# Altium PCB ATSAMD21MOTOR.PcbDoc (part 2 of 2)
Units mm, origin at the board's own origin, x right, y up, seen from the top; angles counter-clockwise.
Board outline 45.2 x 50.2 mm, 4 copper layers (Top Layer, GND, POWER, Bottom Layer), stack 0.8 mm thick; 92 components, 102 nets, 421 pads, 273 vias.
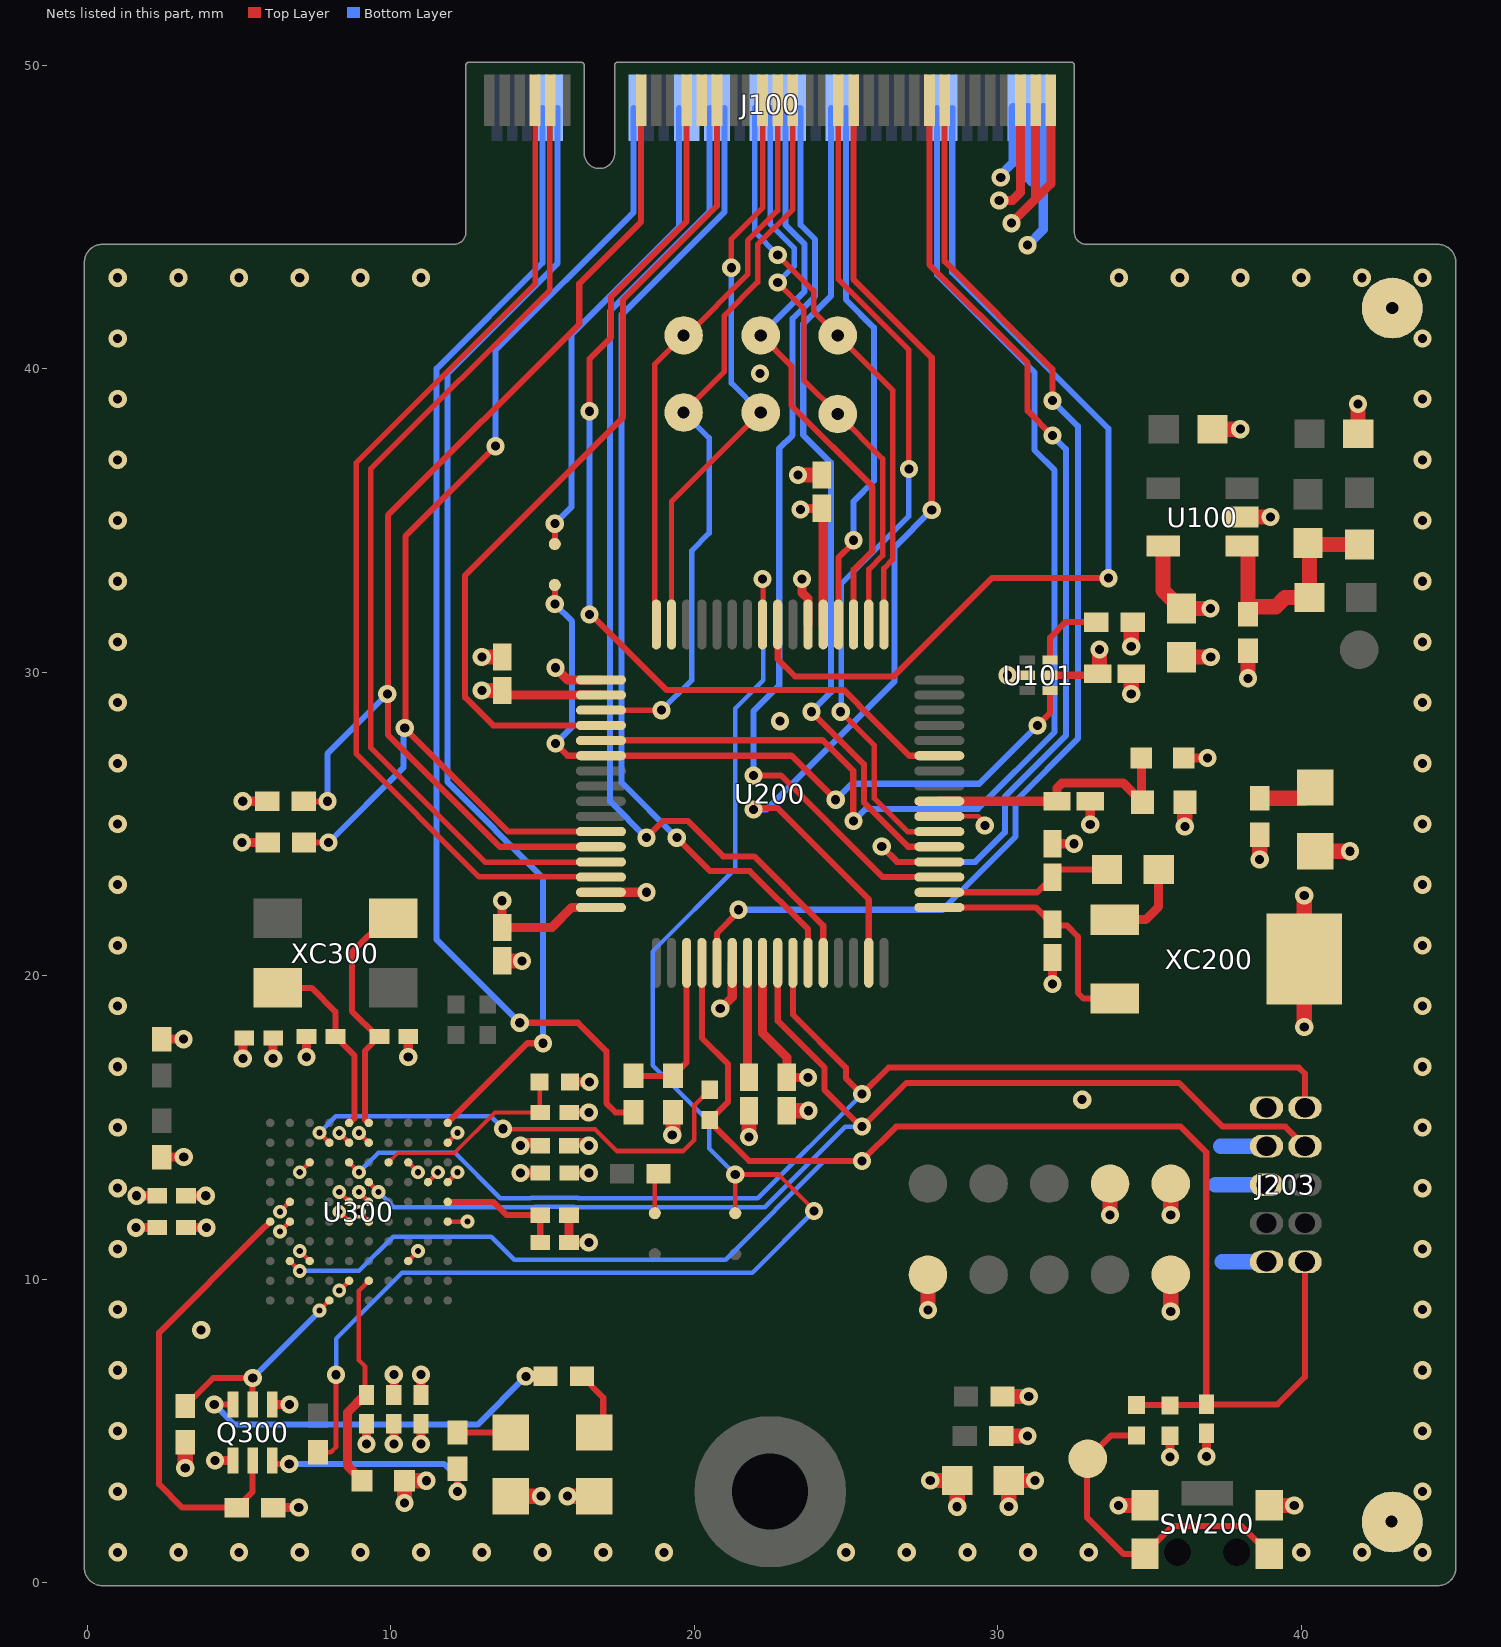
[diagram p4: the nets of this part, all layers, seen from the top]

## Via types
v1: diameter 0.6, hole 0.3, Top Layer to Bottom Layer, 234 vias
v2: diameter 0.457, hole 0.203, Top Layer to Bottom Layer, 30 vias
v3: diameter 0.8, hole 0.4, Top Layer to Bottom Layer, 8 vias
v4: diameter 0.457, hole 0.2, Top Layer to Bottom Layer, 1 vias

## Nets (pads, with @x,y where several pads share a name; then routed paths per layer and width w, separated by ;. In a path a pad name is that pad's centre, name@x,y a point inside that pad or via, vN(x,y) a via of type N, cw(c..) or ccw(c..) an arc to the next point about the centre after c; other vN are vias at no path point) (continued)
GND: C101.2 C102.1 C103.2 C104.2 C200.2 C201.2 C202.2 C203.2 C204.2 C205.2 C206.2 C207.2 C208.2 C209.2 C300.2 C301.2 C302.2 C303.2 C304.2 C305.2 C306.2 C307.2 C308.2 C309.2 C310.2 C311.2 C312.2 J100.64 J100.65 J100.66 J100.67 J203.3 J203.5 J203.9 pad.1 Q300.1 Q300.4 R103.1 R202.1 R204.1 R305.1 R310.1 SW200.2 SW200.4 TP107.1 TP300.1 U100.2 U101.2 U200.7 U200.22 U200.33 U200.47 U200.54 U300.B10 U300.C3 U300.C8 U300.E2 U300.E6 U300.F5 U300.F10 U300.H3 U300.H8 XC200.3 | length 67.9
  Top Layer w0.15: v2(6.351,12.224) U300.E2@6.676,12.549 ; v4(7.001,10.924) U300.H3@7.326,10.599 ; v2(7.001,13.524) U300.C3@7.326,13.849 ; v2(8.301,12.224) U300.F5@8.626,11.899 ; v2(8.951,12.874) U300.E6@9.276,12.549 ; U300.C8@10.576,13.849 v2(10.9,13.525) ; U300.H8@10.576,10.599 v2@10.902,10.925 ; U300.B10@11.876,14.499 v2(12.2,14.825) ; U300.F10@11.876,11.899 v2(12.525,11.899) ; U200.7@28.075,25.25 29.353,25.25 v1@29.653,24.95
  Top Layer w0.2: v1(30.32,29.9) U101.2@30.875,29.9
  Top Layer w0.3: v1@1.53,11.699 C309.2@2.251,11.699 ; v1@1.555,12.749 C311.2@2.276,12.749 ; v1(4.212,4.025) Q300.4@4.8,4.025 ; v1@5.125,17.204 C310.2@5.125,17.925 ; Q300.1@6.1,5.875 v1(6.661,5.875) ; R305.1@6.126,2.473 v1(6.968,2.473) ; v1@7.225,17.254 C300.2@7.225,17.975 ; v1(9.2,4.566) C303.2@9.2,5.235 ; v1(10.1,4.566) C308.2@10.1,5.235 ; v1@10.575,17.254 C301.2@10.575,17.975 ; v1(11,4.566) C312.2@11,5.235 ; v1(15.425,30.149) 15.824,29.75 U200.33@16.925,29.75 ; C305.2@15.876,12.11 C304.2@15.876,11.211 v1@16.597,11.211 ; C307.2@15.876,13.498 v1@16.597,13.498 ; C306.2@15.876,14.498 v1@16.597,14.498 ; C302.2@15.876,15.498 v1@16.597,15.498 ; R310.1@15.901,16.498 v1@16.622,16.498 ; U200.47@16.925,22.75 v1(18.425,22.75) ; v1@20.856,18.9 21.25,19.294 U200.54@21.25,20.425 ; v1(23.55,33.075) 23.55,32.625 23.75,32.425 U200.22@23.75,31.575 ; v1(30.45,44.798) 31.25,45.598 ; J100.65@31.25,48.85 31.25,45.598 ; J100.67@31.75,48.85 31.75,46.098 31.25,45.598 ; v1(31.8,19.723) C200.2@31.8,20.6 ; C201.2@31.8,24.35 v1(32.512,24.35) ; v1(33.05,24.982) C207.2@33.05,25.75 ; v1(36.881,4.157) C202.2@36.881,4.926
  Top Layer w0.5: v1(13,30.5) C204.2@13.676,30.5 ; C205.2@13.67,20.49 v1(14.32,20.49) ; v1(19.275,14.75) 19.3,14.775 R204.1@19.3,15.5 ; v1(21.8,14.682) C208.2@21.8,15.55 ; C206.2@23.05,15.55 v1(23.76,15.55) ; v1(23.418,36.5) C203.2@24.2,36.5 ; R202.1@30.154,6.136 v1(31.021,6.136) ; v1(33.7,12.119) TP300.1@33.7,13.15 ; v1(33.983,2.54) SW200.2@34.85,2.54 ; v1(34.4,29.287) C104.2@34.4,29.95 ; v1(35.7,12.119) TP107.1@35.7,13.15 ; C102.1@36.05,30.5 v1(37.019,30.5) ; v1(36.165,24.916) C209.2@36.165,25.718 ; C103.2@37.075,38.01 v1(37.993,38.01) ; U100.2@38.05,35.115 v1(38.988,35.115) ; v1(38.631,23.834) R103.1@38.631,24.65 ; SW200.4@38.95,2.54 v1(39.771,2.54) ; v1(40.1,18.314) XC200.3@40.1,20.55 v1(40.1,22.647) ; C101.2@41.875,37.86 v1(41.875,38.841)
  Bottom Layer w0.3: v1(30.984,44.074) 31.5,44.589 31.5,46.15 ; J100.64@31,48.6 31,46.279 31.129,46.15 31.5,46.15 ; J100.66@31.5,48.6 31.5,46.15
  Bottom Layer w0.5: 37.166,13.114 J203.5@38.856,13.114 ; 37.344,14.384 J203.3@38.856,14.384 ; 37.387,10.574 J203.9@38.856,10.574
  other v1: 1,1 3,1 5,1 7,1 9,1 11,1 13,1 15,1 17,1 19,1 25,1 27,1 29,1 31,1 33,1 40,1 42,1 44,1 1,3 44,3 1,5 44,5 1,7 44,7 3.751,8.326 1,9 44,9 1,11 44,11 16.526,11.211 1.601,11.699 1.626,12.749 1,13 44,13 16.526,13.498 16.525,14.4 1,15 44,15 16.526,15.498 32.782,15.916 16.551,16.498 1,17 44,17 5.125,17.275 7.225,17.325 10.575,17.325 20.856,18.925 1,19 44,19 1,21 44,21 1,23 44,23 29.575,24.95 1,25 44,25 1,27 44,27 22.825,28.389 1,29 44,29 1,31 44,31 1,33 44,33 1,35 44,35 1,37 44,37 1,39 44,39 22.168,39.841 1,41 44,41 1,43 3,43 5,43 7,43 9,43 11,43 34,43 36,43 38,43 40,43 42,43 44,43
  other v2: 10.901,10.927
  other v3: 42.974,2.014 43,42
GPIO1: J102.1 U101.4 U200.38 | length 24.7
  Top Layer w0.2: v1(15.406,32.245) J102.1@15.406,32.875 ; v1(15.425,27.65) 15.825,27.25 U200.38@16.925,27.25 23.208,27.25 v1(24.66,25.798) ; v1(31.315,28.25) 31.725,28.66 U101.4@31.725,29.4
  Bottom Layer w0.2: v1(15.406,32.245) 15.975,31.676 15.975,28.2 v1(15.425,27.65) ; v1(24.66,25.798) 25.188,26.326 29.391,26.326 v1(31.315,28.25)
GPIO2: J100.19 U200.11 | length 31.6
  Top Layer w0.2: v1(16.55,38.6) 16.55,40.329 17.259,41.038 17.259,42.371 19.75,44.862 J100.19@19.75,48.85 ; v1@16.6,31.9 19.088,29.412 24.941,29.412 25.425,28.928 25.425,28.916 27.091,27.25 U200.11@28.075,27.25
  Bottom Layer w0.2: v1@16.55,31.95 v1(16.55,38.6)
  other v1: 16.55,31.9
GPIO3: J100.20
GPIO4: J100.21
GPIO5: J100.22 U200.60 | length 34.6
  Top Layer w0.2: v1(18.425,24.55) 18.975,25.1 19.785,25.1 20.954,23.93 21.974,23.93 24.25,21.654 U200.60@24.25,20.425
  Bottom Layer w0.2: v1(18.425,24.55) 17.228,25.747 17.228,41.908 20.5,45.18 J100.22@20.5,48.6
GPIO6: J100.23 U200.36 | length 28
  Top Layer w0.2: U200.36@16.925,28.25 13.372,28.25 12.45,29.172 12.45,33.191 17.65,38.391 17.65,42.267 20.75,45.367 J100.23@20.75,48.85
GPIO7: J100.24 U200.59 | length 32.9
  Top Layer w0.2: v1(19.425,24.55) 20.528,23.447 21.828,23.447 23.75,21.526 U200.59@23.75,20.425
  Bottom Layer w0.2: v1(19.425,24.55) 17.607,26.368 17.607,41.782 21,45.175 J100.24@21,48.6
HALL1: J100.51 U200.4 | length 33.6
  Top Layer w0.2: v1(26.178,24.259) 26.687,23.75 U200.4@28.075,23.75 ; J100.51@27.75,48.85 27.75,43.432 30.986,40.195 30.986,38.614 v1(31.8,37.8)
  Bottom Layer w0.2: v1(26.178,24.259) 26.687,23.75 29.259,23.75 30.236,24.727 30.236,25.898 32.247,27.91 32.247,37.353 v1(31.8,37.8)
HALL2: J100.52 U200.37 | length 40.4
  Top Layer w0.2: U200.37@16.925,27.75 16.935,27.76 24.229,27.76 25.238,26.751 25.238,25.112 v1(25.25,25.1)
  Bottom Layer w0.2: v1(25.25,25.1) 25.65,25.5 29.343,25.5 31.875,28.032 31.875,36.653 31.211,37.317 31.211,39.882 28,43.093 J100.52@28,48.6
HALL3: J100.53 U200.53 | length 39.1
  Top Layer w0.2: U200.53@20.75,20.425 20.75,21.397 21.455,22.102 v1(21.455,22.175) ; J100.53@28.25,48.85 28.25,43.537 31.8,39.987 v1(31.8,38.95)
  Bottom Layer w0.2: v1(21.455,22.175) 28.179,22.175 30.586,24.582 30.586,25.753 32.643,27.811 32.643,38.107 v1(31.8,38.95)
HALL_TRX_OE: J100.54 U200.24 | length 31.3
  Top Layer w0.2: U200.24@22.8,31.625 U200.24@22.75,31.575 22.75,30.435 23.319,29.866 26.573,29.866 29.807,33.1 v1(33.65,33.1)
  Bottom Layer w0.2: J100.54@28.5,48.6 28.5,43.177 33.65,38.027 v1(33.65,33.1)
ISENSE_COMMON: J100.34 U200.3 | length 30.6
  Top Layer w0.2: v1(21.95,26.6) 22.857,26.6 26.207,23.25 U200.3@28.075,23.25
  Bottom Layer w0.2: v1(21.95,26.6) 21.95,28.719 22.8,29.569 22.8,37.375 23.242,37.817 23.242,41.657 23.98,42.395 23.98,44.259 23.5,44.739 J100.34@23.5,48.6
MCU_USB_N: J100.9 U200.45 | length 32.9
  Top Layer w0.18: J100.9@15.25,48.85 15.25,48.373 15.24,48.363 15.24,42.602 9.346,36.708 9.346,27.506 13.112,23.74 16.915,23.74 U200.45@16.925,23.75
MCU_USB_P: J100.7 U200.46 | length 33.7
  Top Layer w0.18: J100.7@14.75,48.85 14.75,48.421 14.76,48.411 14.76,42.801 8.866,36.907 8.866,27.307 12.913,23.26 16.915,23.26 U200.46@16.925,23.25
MOTOR_VDC: J100.41 U200.63 | length 34.3
  Top Layer w0.2: v1(21.95,25.475) 21.997,25.522 22.747,25.522 25.75,22.519 U200.63@25.75,20.425 ; J100.41@25.25,48.85 25.25,42.94 27.825,40.365 v1(27.825,35.35)
  Bottom Layer w0.2: v1(21.95,25.475) 22.378,25.475 26.601,29.698 26.601,34.126 v1(27.825,35.35)
NetC100_2: C100.2 R100.2 R101.1 R102.1 U100.1 | length 7.7
  Top Layer w0.5: U100.1@38.05,34.165 38.25,33.964 38.25,32.16 39.166,32.16 39.465,32.46 R102.1@40.275,32.46 C100.2@40.275,34.21 ; C100.2@40.225,34.26 C100.2@40.275,34.21 ; R100.2@41.925,34.21 C100.2@40.275,34.21
NetC302_1: C302.1 R310.2 U300.C7 | length 6.7
  Top Layer w0.125: U300.C7@9.926,13.849 10.229,14.152 12.086,14.152 13.433,15.498 C302.1@14.926,15.498
  Top Layer w0.15: C302.1@14.901,15.523 R310.2@14.901,16.498
NetC303_1: C303.1 L300.2 U300.J6 | length 7.2
  Top Layer w0.15: C303.1@9.151,6.185 9.151,7.128 8.951,7.327 8.951,9.624 U300.J6@9.276,9.949
  Top Layer w0.3: L300.2@9.058,3.373 8.57,3.861 8.57,5.605 C303.1@9.151,6.185
NetC304_1: C304.1 C305.1 U300.E10 | length 4.1
  Top Layer w0.2: U300.E10@11.876,12.549 13.376,12.549 13.815,12.11 C305.1@14.926,12.11 C304.1@14.926,11.211
NetD100_1: D100.1 R103.2 | length 2
  Top Layer w0.5: R103.2@38.631,25.85 40.113,25.85 D100.1@40.465,26.203
NetD300_1: D300.1 R303.2 | length 1.8
  Top Layer w0.2: R303.2@12.2,4.95 D300.1@13.95,4.95
NetD301_1: D301.1 R304.2 | length 2.4
  Top Layer w0.2: R304.2@16.15,6.65 R304.2@16.3,6.8 17,6.1 D301.1@17,4.95
NetJ100_18: J100.18 J102.2 | length 16.1
  Top Layer w0.2: J102.2@15.406,34.225 v1(15.406,34.896)
  Bottom Layer w0.2: v1(15.406,34.896) 15.95,35.44 15.95,41.125 19.5,44.675 J100.18@19.5,48.6
NetJ201_2: J201.2 R306.1 | length 1.3
  Top Layer w0.15: J201.2@18.7,12.175 18.7,13.355 R306.1@18.819,13.474
NetJ202_1: J202.1 XC200.1 | length 2.8
  Top Layer w0.3: XC200.1@33.85,21.85 34.872,21.85 35.3,22.278 J202.1@35.3,23.5
NetQ300_3: Q300.3 R304.1 | length 12.5
  Top Layer w0.2: v1(4.184,5.875) Q300.3@4.8,5.875 ; v1(14.45,6.8) R304.1@15.1,6.8
  Bottom Layer w0.2: v1(4.184,5.875) 4.849,5.21 12.86,5.21 v1(14.45,6.8)
NetQ300_6: Q300.6 R303.1 | length 7.5
  Top Layer w0.2: Q300.6@6.1,4.025 6.215,3.91 v1(6.654,3.91) ; v1(12.2,3.005) R303.1@12.2,3.75
  Bottom Layer w0.2: v1(6.654,3.91) 11.759,3.91 12.2,3.469 v1(12.2,3.005)
NetR104_1: R104.1 U101.6 | length 2.5
  Top Layer w0.2: U101.6@31.725,30.4 31.725,31.144 32.231,31.65 R104.1@33.25,31.65
NetR208_1: R208.1 SW200.1 SW200.5 TP200.1 | length 11.9
  Top Layer w0.2: TP200.1@33.187,4.085 33.078,4.194 TP200.1@32.97,4.303 ; R208.1@34.573,4.852 33.736,4.852 TP200.1@32.97,4.085 TP200.1@32.97,4.303 ; SW200.1@34.85,0.94 34.148,0.94 32.945,2.143 32.945,4.318 32.955,4.318 TP200.1@32.97,4.303 ; SW200.1@34.85,0.95 35.772,1.872 38.028,1.872 SW200.5@38.95,0.95
PA00_XIN32: C200.1 U200.1 XC200.2 | length 7.8
  Top Layer w0.2: U200.1@28.075,22.25 31.25,22.25 C200.1@31.8,21.7 ; 32.1,21.65 32.284,21.65 32.641,21.293 32.641,19.431 32.822,19.25 XC200.2@33.85,19.25
PA01_XOUT32: C201.1 J202.2 U200.2 | length 5.8
  Top Layer w0.2: U200.2@28.075,22.75 31.3,22.75 C201.1@31.8,23.25 32.05,23.5 J202.2@33.6,23.5
PA08_TCC0_WO0: J100.28 TP100.1 U200.17 | length 19
  Top Layer w0.18: v1(22.75,43.75) 23.935,42.565 23.935,41.895 v3(24.73,41.1) 26.535,39.295 26.535,33.708 26.25,33.423 U200.17@26.25,31.575
  Bottom Layer w0.18: J100.28@22,48.6 22,44.5 v1(22.75,43.75)
PA09_TCC0_WO1: J100.30 TP102.1 U200.18 | length 19.2
  Top Layer w0.18: v1(22.75,42.839) 23.605,41.985 23.605,39.635 v3(24.73,38.51) 26.205,37.035 26.205,33.845 25.75,33.39 U200.18@25.75,31.575
  Bottom Layer w0.18: J100.30@22.5,48.6 22.5,44.764 23.29,43.974 23.29,43.379 v1(22.75,42.839)
PA10_TCC0_WO2: J100.32 TP104.1 U200.19 | length 19.7
  Top Layer w0.2: v3(22.19,41.1) 23.198,40.092 23.198,38.79 25.865,36.123 25.865,33.996 25.25,33.381 U200.19@25.25,31.575
  Bottom Layer w0.2: v3(22.19,41.1) 23.63,42.54 23.63,44.115 23,44.745 J100.32@23,48.6
PA11_ADC_AIN19: J100.40 U200.20 | length 17.9
  Top Layer w0.2: U200.20@24.75,31.575 24.75,33.775 25.25,34.275 v1(25.25,34.35)
  Bottom Layer w0.2: J100.40@25,48.6 25,42.277 25.919,41.358 25.919,36.302 25.25,35.633 v1(25.25,34.35)
PA14_TCC0_WO4: J100.29 TP101.1 U200.31 | length 19.3
  Top Layer w0.18: U200.31@19.25,31.575 19.25,35.62 v3(22.19,38.56) ; v1(21.221,43.331) 21.221,44.275 22.25,45.304 J100.29@22.25,48.85
  Bottom Layer w0.18: v1(21.221,43.331) 21.221,39.529 v3(22.19,38.56)
PA15_TCC0_WO5: J100.31 TP103.1 U200.32 | length 19.3
  Top Layer w0.18: U200.32@18.75,31.575 18.697,31.628 18.697,40.148 v3(19.65,41.1) 19.754,41.1 21.761,43.107 21.761,44.225 22.75,45.214 J100.31@22.75,48.85 ; TP103.1@19.83,40.92 20,41.09 TP103.1@20,41.1
PA16_TCC0_WO6: J100.33 TP105.1 U200.35 | length 24.6
  Top Layer w0.18: U200.35@16.925,28.75 v1(18.925,28.75) ; v3(19.65,38.56) 20.985,39.895 20.985,41.746 22.091,42.852 22.091,44.088 23.25,45.247 J100.33@23.25,48.85
  Bottom Layer w0.18: v1(18.925,28.75) 19.91,29.735 19.91,34.001 20.49,34.581 20.49,37.72 v3(19.65,38.56)
PA22_S3_PAD0: J100.12 R206.1 U200.43 | length 37.1
  Top Layer w0.2: R206.1@7.143,24.391 v1(7.949,24.391) ; v1(13.45,37.45) 10.48,34.48 10.48,28.181 v1(10.46,28.161) 13.871,24.75 U200.43@16.925,24.75
  Bottom Layer w0.2: v1(7.949,24.391) 10.414,26.856 10.414,28.115 v1(10.46,28.161) ; v1(13.45,37.45) 13.45,40.605 18,45.155 J100.12@18,48.6
PA23_S3_PAD1: J100.13 R205.1 U200.44 | length 38.1
  Top Layer w0.2: R205.1@7.129,25.748 v1(7.911,25.748) ; U200.44@16.925,24.25 13.593,24.25 9.904,27.939 9.904,35.168 16.209,41.473 16.209,42.806 18.25,44.847 J100.13@18.25,48.85
  Bottom Layer w0.2: v1(7.911,25.748) 7.911,27.309 v1(9.886,29.284)
PA27_USB_VBUS: R203.1 R204.2 U200.51 | length 5.2
  Top Layer w0.2: R203.1@18,16.7 R204.2@19.3,16.7 19.75,17.15 U200.51@19.75,20.425
PA30_SWDCLK: J203.4 U200.57 U300.D6 | length 40.3
  Top Layer w0.15: U300.D6@9.276,13.199 v2(9.6,12.875)
  Top Layer w0.2: U200.57@22.75,20.425 22.75,18.514 24.293,16.97 24.293,16.232 25.525,15 26.991,16.466 35.975,16.466 37.412,15.029 39.481,15.029 J203.4@40.126,14.384
  Bottom Layer w0.15: v2(9.6,12.875) 10.102,12.373 14.742,12.373 14.751,12.382 16.051,12.382 16.06,12.373 22.319,12.373 24.975,15.029 v1(25.525,15.029)
PA31_SWDIO: J203.2 U200.58 U300.C5 | length 40.8
  Top Layer w0.15: U300.C5@8.626,13.849 v2(8.95,13.525)
  Top Layer w0.2: U200.58@23.25,20.425 23.25,18.723 24.998,16.975 24.998,16.627 v1(25.525,16.1) 26.4,16.975 39.922,16.975 40.126,16.771 J203.2@40.126,15.654
  Bottom Layer w0.15: v2(8.95,13.525) 9.586,14.161 12.119,14.161 13.607,12.673 14.618,12.673 14.627,12.682 16.175,12.682 16.184,12.673 22.098,12.673 v1(25.525,16.1)
PB04_ADC_AIN12: J100.38 U200.5 | length 27.7
  Top Layer w0.2: v1@23.858,28.723 v1(23.858,28.7) 25.588,26.97 25.588,25.712 27.05,24.25 U200.5@28.075,24.25
  Bottom Layer w0.2: v1(23.858,28.7) 24.5,29.342 24.5,36.904 23.592,37.812 23.592,41.484 24.5,42.392 J100.38@24.5,48.6
PB05_ADC_AIN13: J100.39 U200.6 | length 28
  Top Layer w0.18: J100.39@24.75,48.85 24.75,42.948 27.075,40.623 v1(27.075,36.7) ; v1(24.825,28.7) 25.928,27.597 25.928,25.853 27.031,24.75 U200.6@28.075,24.75
  Bottom Layer w0.18: v1(24.825,28.7) 24.84,28.715 24.84,32.909 27.075,35.144 v1(27.075,36.7)
PB12_S4_PAD0: J200.1 R307.2 U200.25 | length 49.9
  Top Layer w0.15: R307.2@7.6,4.3 8.025,4.3 8.195,4.47 8.195,6.849 v1(8.196,6.85) ; J200.1@21.35,12.175 v1(21.35,13.45) 22.775,13.45 v1@23.962,12.263 ; U200.25@22.25,31.575 v1@22.25,33
  Bottom Layer w0.15: v1(8.196,6.85) 8.196,8.044 10.37,10.217 21.917,10.217 v1(23.95,12.25) 23.95,12.291 23.958,12.298 v1@23.978,12.278 ; v1(21.35,13.45) 20.493,14.307 20.493,15.182 18.625,17.05 18.625,20.798 21.35,23.523 21.35,28.808 22.275,29.733 22.275,33.05 v1(22.25,33.075)
POWER_LED_CTRL: Q300.2 R302.1 U300.K4 | length 7.1
  Top Layer w0.15: v2(7.651,8.974) U300.K4@7.976,9.299
  Top Layer w0.2: R302.1@3.226,5.823 4.147,6.744 v1(5.45,6.744) Q300.2@5.45,5.875
  Bottom Layer w0.2: v1(5.45,6.744) 7.651,8.945 v2(7.651,8.974)
STATUS_LED_CTRL: Q300.5 R305.2 U300.F1 | length 14.8
  Top Layer w0.2: Q300.5@5.45,4.025 5.45,2.997 R305.2@4.926,2.473 3.134,2.473 2.363,3.244 2.363,8.236 5.701,11.574 U300.F1@6.026,11.899
TARGET_RESET: R200.1 U300.B4 | length 15.2
  Top Layer w0.15: v2(7.65,14.825) U300.B4@7.975,14.5 ; v1@13.974,14.937 16.731,14.937 17.442,14.225 19.633,14.225 19.996,14.588 19.996,15.725 R200.1@20.514,16.243
  Bottom Layer w0.15: v2(7.65,14.825) 8.19,15.365 13.294,15.365 v1(13.701,14.958)
TARGET_RESET_SENSE: C202.1 J203.10 R200.2 R207.1 R208.2 U200.52 U300.H2 | length 62.7
  Top Layer w0.15: U300.H2@6.675,10.6 v2(7,10.275)
  Top Layer w0.2: U200.52@20.25,20.425 20.25,17.949 21.116,17.083 21.116,15.845 R200.2@20.514,15.243 20.514,15.189 21.804,13.9 v1(25.525,13.9) 26.654,15.029 36.025,15.029 36.87,14.184 36.87,5.887 C202.1@36.881,5.876 ; R208.2@34.573,5.852 36.857,5.852 C202.1@36.881,5.876 ; J203.10@40.126,10.574 40.126,6.783 39.218,5.876 C202.1@36.881,5.876
  Bottom Layer w0.15: v2(7,10.275) 8.952,10.275 10.081,11.404 13.308,11.404 14.067,10.646 21.033,10.646 24.287,13.9 v1(25.525,13.9)
VCC_EDBG_P3V3: C306.1 C307.1 C308.1 C309.1 C310.1 C311.1 C312.1 D300.2 D301.2 L300.1 R300.2 R301.2 R302.2 R311.1 TP307.1 U300.B5 U300.B6 U300.D9 U300.D10 U300.E5 U300.F2 U300.F6 U300.J5 | length 17.4
  Top Layer w0.15: v2(6.351,11.574) U300.F2@6.676,11.899 ; v2(8.301,9.624) U300.J5@8.626,9.949 ; v2(8.301,12.874) U300.E5@8.626,12.549 ; v2(8.301,14.824) U300.B5@8.626,14.499 ; v2(8.951,12.224) U300.F6@9.276,11.899 ; v2(8.951,14.824) U300.B6@9.276,14.499 ; U300.D9@11.226,13.199 v2(11.55,13.525) ; U300.D10@11.876,13.199 v2(12.2,13.525)
  Top Layer w0.3: R300.2@2.45,17.91 v1(3.17,17.91) ; R301.2@2.452,14.022 v1(3.178,14.022) ; C311.1@3.251,12.749 v1@3.972,12.749 ; C309.1@3.276,11.699 v1@3.997,11.699 ; v1@6.125,17.204 C310.1@6.125,17.925 ; C308.1@10.1,6.185 v1(10.1,6.854) ; C312.1@11,6.185 v1(11,6.854) ; v1@14.205,13.498 C307.1@14.926,13.498 ; v1@14.276,14.498 C306.1@14.926,14.498
  Top Layer w0.5: v1(3.226,3.783) R302.2@3.226,4.623 ; v1(10.45,2.627) L300.1@10.45,3.36 v1(11.171,3.36) ; D300.2@13.95,2.85 v1(14.956,2.85) ; v1(15.827,2.85) D301.2@17,2.85 ; v1(27.7,8.988) TP307.1@27.7,10.15 ; v1(27.776,3.368) R311.1@28.663,3.368 v1(28.663,2.501)
  other v1: 3.926,11.699 3.901,12.749 14.276,13.498 14.275,14.4 6.125,17.275
VCC_EDBG_USB_P5V0: J100.10 U300.A10 | length 37.9
  Top Layer w0.2: U300.A10@11.876,15.149 14.501,17.774 v1(15.012,17.774)
  Bottom Layer w0.2: v1(15.012,17.774) 15.012,23.236 11.862,26.385 11.862,39.839 15.5,43.476 J100.10@15.5,48.6
VCC_MCU_CORE: C208.1 U200.55 | length 3.8
  Top Layer w0.3: U200.55@21.75,20.425 21.75,16.7 C208.1@21.8,16.65
VCC_MCU_VDDANA: C207.1 C209.1 L200.2 U200.8 | length 8.9
  Top Layer w0.3: U200.8@28.075,25.75 C207.1@31.95,25.75 31.95,26.18 32.12,26.35 34.136,26.35 C209.1@34.732,25.754 ; L200.2@34.732,27.171 C209.1@34.732,25.754 ; C209.1@34.768,25.718 C209.1@34.732,25.754
VCC_TARGET_P3V3: C102.2 C104.1 C203.1 C204.1 C205.1 C206.1 D100.2 J100.62 J100.63 J203.1 L200.1 R101.2 R104.2 R201.2 R205.2 R206.2 R207.2 R311.2 TP108.1 U100.5 U101.5 U200.21 U200.34 U200.48 U200.56 | length 39.7
  Top Layer w0.25: U101.5@31.725,29.9 33.25,29.9 C104.1@33.3,29.95
  Top Layer w0.3: v1(5.096,24.391) R206.2@5.943,24.391 ; v1(5.122,25.748) R205.2@5.929,25.748 ; v1(13.67,22.472) C205.1@13.67,21.59 15.306,21.59 15.966,22.25 U200.48@16.925,22.25 ; C204.1@13.676,29.4 13.826,29.25 U200.34@16.925,29.25 ; U200.56@22.25,20.425 22.25,18.108 23.05,17.308 C206.1@23.05,16.65 v1(23.743,16.65) ; v1@23.437,35.4 C203.1@24.2,35.4 24.25,35.35 U200.21@24.25,31.575 ; v1(30.05,45.55) 30.487,45.55 30.75,45.813 J100.63@30.75,48.85 ; v1(35.675,4.146) R207.2@35.675,4.839 ; L200.1@36.132,27.171 v1(36.908,27.171)
  Top Layer w0.5: v1(13,29.4) C204.1@13.676,29.4 ; R201.2@30.113,4.835 v1(30.98,4.835) ; v1(30.363,2.504) R311.2@30.363,3.368 v1(31.228,3.368) ; C104.1@33.35,30 v1(33.35,30.75) ; v1(34.4,30.85) 34.4,31.6 R104.2@34.45,31.65 ; U100.5@35.45,34.165 35.45,32.7 C102.2@36.05,32.1 v1(37.011,32.1) ; v1(35.7,8.939) TP108.1@35.7,10.15 ; v1(38.25,29.8) R101.2@38.25,30.71 ; D100.2@40.465,24.103 v1(41.605,24.103)
  Bottom Layer w0.3: v1(30.1,46.3) 30.013,46.3 30.5,46.787 J100.62@30.5,48.6
  other v1: 23.5,35.36
VCC_TARGET_USB_P5V0: J100.8 R203.2 | length 38.9
  Top Layer w0.2: v1(14.25,18.45) 16.166,18.45 17.101,17.515 17.101,15.803 17.404,15.5 R203.2@18,15.5 R203.2@18,15.692
  Bottom Layer w0.2: v1(14.25,18.45) 11.512,21.188 11.512,40.005 15,43.492 J100.8@15,48.6
XIN0: C300.1 U300.A5 XC300.1 | length 6.2
  Top Layer w0.2: XC300.1@6.276,19.599 7.39,19.599 8.175,18.814 C300.1@8.175,18 8.8,17.375 8.8,15.298 U300.A5@8.626,15.124
XOUT0: C301.1 U300.A6 XC300.3 | length 8.1
  Top Layer w0.2: U300.A6@9.276,15.123 9.15,15.249 9.15,17.525 C301.1@9.625,18 9.552,18 8.719,18.833 8.719,20.772 9.846,21.899 XC300.3@10.076,21.899
pads on no net: J100.2 J100.5 J100.11 J100.59 J100.60 J100.61 J203.6 J203.7 J203.8 SW200.3 SW200.6 SW200.7 U300.A2 U300.A3 U300.A4 U300.A7 U300.B1 U300.B3 U300.B7 U300.C1 U300.C2 U300.C4 U300.C6 U300.C9 U300.C10 U300.D1 U300.D2 U300.D3 U300.D4 U300.D5 U300.D7 U300.D8 U300.E1 U300.E3 U300.E4 U300.E7 U300.E8 U300.F3 U300.F4 U300.F7 U300.F8 U300.G1 U300.G2 U300.G3 U300.G4 U300.G6 U300.G7 U300.G8 U300.G9 U300.G10 U300.H1 U300.H4 U300.H5 U300.H6 U300.H10 U300.J1 U300.J2 U300.J3 U300.J7 U300.J10 U300.K1 U300.K5 U300.K6 U300.K7 XC300.2 XC300.4

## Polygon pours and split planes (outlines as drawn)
GND on Top Layer "Mechanical 1-No Net" (solid, remove dead copper, pour order 4): -0.4,-1.776 -0.4,50.32 43.687,50.32 45.153,50.32 45.153,-1.762
GND on Bottom Layer "Mechanical 1-No Net" (solid, remove dead copper, pour order 3): -0.4,-1.776 -0.4,50.32 43.687,50.32 45.153,50.32 45.153,-1.762
GND on GND (split plane): 32.224,44.5 32.223,44.5 32.232,44.39 32.258,44.283 32.3,44.181 32.357,44.088 32.429,44.004 32.512,43.932 32.606,43.875 32.708,43.833 32.815,43.807 32.925,43.798 32.925,43.799 44.5,43.799 44.502,43.799 44.558,43.794 44.615,43.776 44.666,43.749 44.712,43.712 44.749,43.666 44.776,43.615 44.794,43.558 44.799,43.502 44.799,43.5 44.799,0.5 44.799,0.498 44.794,0.442 44.776,0.385 44.749,0.334 44.712,0.288 44.666,0.251 44.615,0.223 44.558,0.206 44.502,0.201 44.5,0.201 0.5,0.201 0.499,0.201 0.497,0.201 0.442,0.206 0.385,0.223 0.334,0.251 0.288,0.288 0.251,0.334 0.223,0.385 0.206,0.442 0.201,0.498 0.201,0.5 0.201,43.5 0.201,43.502 0.206,43.558 0.223,43.615 0.251,43.666 0.288,43.712 0.334,43.749 0.385,43.776 0.442,43.794 0.498,43.799 0.5,43.799 12.075,43.799 12.075,43.798 12.185,43.807 12.292,43.833 12.394,43.875 12.487,43.932 12.571,44.004 12.643,44.088 12.7,44.181 12.742,44.283 12.768,44.39 12.777,44.5 12.776,44.5 12.776,49.799 16.074,49.799 16.074,47.1 16.073,47.1 16.083,46.975 16.112,46.852 16.16,46.736 16.226,46.629 16.308,46.533 16.404,46.451 16.511,46.385 16.627,46.337 16.75,46.308 16.875,46.298 17,46.308 17.123,46.337 17.239,46.385 17.346,46.451 17.442,46.533 17.524,46.629 17.59,46.736 17.638,46.852 17.667,46.975 17.677,47.1 17.676,47.1 17.676,49.799 32.224,49.799
VCC_EDBG_P3V3 on POWER (split plane): 22.942,11.197 22.994,11.157 23.055,11.132 23.12,11.123 29.27,11.123 29.27,0.201 0.5,0.201 0.499,0.201 0.497,0.201 0.442,0.206 0.385,0.223 0.334,0.251 0.288,0.288 0.251,0.334 0.223,0.385 0.206,0.442 0.201,0.498 0.201,0.5 0.201,22.903 11.235,22.903
VCC_TARGET_P3V3 on POWER (split plane): 32.224,44.5 32.223,44.5 32.232,44.39 32.258,44.283 32.3,44.181 32.357,44.088 32.429,44.004 32.512,43.932 32.606,43.875 32.708,43.833 32.815,43.807 32.925,43.798 32.925,43.799 44.5,43.799 44.502,43.799 44.558,43.794 44.615,43.776 44.666,43.749 44.712,43.712 44.749,43.666 44.776,43.615 44.794,43.558 44.799,43.502 44.799,43.5 44.799,0.5 44.799,0.498 44.794,0.442 44.776,0.385 44.749,0.334 44.712,0.288 44.666,0.251 44.615,0.223 44.558,0.206 44.502,0.201 44.5,0.201 29.775,0.201 29.775,11.375 29.766,11.44 29.741,11.501 29.701,11.553 29.649,11.594 29.588,11.619 29.523,11.627 23.224,11.627 11.518,23.334 11.466,23.374 11.405,23.399 11.34,23.407 0.201,23.407 0.201,43.5 0.201,43.502 0.206,43.558 0.223,43.615 0.251,43.666 0.288,43.712 0.334,43.749 0.385,43.776 0.442,43.794 0.498,43.799 0.5,43.799 12.075,43.799 12.075,43.798 12.185,43.807 12.292,43.833 12.394,43.875 12.487,43.932 12.571,44.004 12.643,44.088 12.7,44.181 12.742,44.283 12.768,44.39 12.777,44.5 12.776,44.5 12.776,49.799 16.074,49.799 16.074,47.1 16.073,47.1 16.083,46.975 16.112,46.852 16.16,46.736 16.226,46.629 16.308,46.533 16.404,46.451 16.511,46.385 16.627,46.337 16.75,46.308 16.875,46.298 17,46.308 17.123,46.337 17.239,46.385 17.346,46.451 17.442,46.533 17.524,46.629 17.59,46.736 17.638,46.852 17.667,46.975 17.677,47.1 17.676,47.1 17.676,49.799 32.224,49.799

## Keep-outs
Keep-Out Layer:
  circle w0.2: c22.5,3 r2.4
  lines w0.2: 0.5,0 ccw(c0.5,0) 0.5,0 ; 0.5,0 cw(c0.5,0.5) 0,0.5 0,43.5 cw(c0.5,43.5) 0.5,44 12.075,44 ccw(c12.075,44.5) 12.575,44.5 12.575,50 16.275,50 16.275,47.1 ccw(c16.875,47.1) 16.875,46.5 ccw(c16.875,47.1) 17.475,47.1 17.475,50 32.425,50 32.425,44.5 ccw(c32.925,44.5) 32.925,44 44.5,44 cw(c44.5,43.5) 45,43.5 45,0.5 cw(c44.5,0.5) 44.5,0 0.5,0 ; 0.5,0 0.5,0

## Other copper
Top Layer:
  pour cut-out: 37.331,4.401 34.102,4.401 34.102,6.401 37.331,6.401
  pour cut-out: 4.801,8.074 4.801,16.374 13.101,16.374 13.101,8.074
  pour cut-out: 2.567,6.473 3.801,6.473 3.801,3.958 2.534,3.958
  pour cut-out: 4.1,3.35 6.8,3.35 6.8,6.55 4.1,6.55
  pour cut-out: 6.75,3.65 8.175,3.65 8.175,6.15 6.75,6.15
  pour cut-out: 8.45,2.76 11.05,2.76 11.05,3.96 8.45,3.96
  pour cut-out: 4.276,1.898 6.78,1.898 6.78,3.35 4.276,3.35
  pour cut-out: 11.625,3.1 12.775,3.1 12.775,5.6 11.625,5.6
  pour cut-out: 12.95,2.05 17.711,2.05 17.711,6.059 12.95,6.059
  pour cut-out: 15.7,2.05 17.7,2.05 17.7,6.059 15.7,6.059
  pour cut-out: 14.416,6.26 16.916,6.26 16.916,7.361 14.416,7.361
  pour cut-out: 34.225,0.3 39.575,0.3 39.575,3.5 34.225,3.5
  pour cut-out: 27.913,2.643 31.113,2.643 31.113,4.093 27.913,4.093
  pour cut-out: 41.491,16.614 37.491,16.614 37.491,9.614 41.491,9.614
  pour cut-out: 32.85,18.55 41.55,18.55 41.55,22.55 32.85,22.55
  pour cut-out: 17.425,14.85 23.6,14.85 23.6,17.35 17.425,17.35
  pour cut-out: 13.12,19.79 14.22,19.79 14.22,22.29 13.12,22.29
  pour cut-out: 13.126,28.7 14.226,28.7 14.226,31.2 13.126,31.2
  pour cut-out: 23.65,34.7 24.75,34.7 24.75,37.204 23.646,37.204
  pour cut-out: 34.55,33.365 39.55,33.365 39.55,36.865 34.55,36.865
  pour cut-out: 34.725,37.285 37.829,37.285 37.829,38.735 34.725,38.735
  pour cut-out: 39.525,37.135 42.625,37.135 42.625,38.585 39.525,38.585
  pour cut-out: 39.5,33.51 42.65,33.51 42.65,36.61 39.5,36.61
  pour cut-out: 5.293,23.816 5.293,24.966 7.793,24.966 7.793,23.816
  pour cut-out: 5.279,25.173 5.279,26.323 7.779,26.323 7.779,25.173
  pour cut-out: 13.126,28.7 13.126,31.204 14.226,31.204 14.226,28.7
  pour cut-out: 35.271,29.746 35.271,32.85 36.729,32.85 36.729,29.746
  pour cut-out: 37.525,29.71 37.525,32.91 38.975,32.91 38.975,29.71
  pour cut-out: 39.525,31.735 39.525,33.185 42.725,33.185 42.725,31.735
  pour cut-out: 12.591,46.329 32.422,46.329 32.422,49.629 12.578,49.629
  pour cut-out: 32.85,22.775 32.85,24.225 36.05,24.225 36.05,22.775
  pour cut-out: 31.246,19.896 31.246,22.4 32.354,22.4 32.354,19.896
  pour cut-out: 31.25,22.55 31.25,25.05 32.35,25.05 32.35,22.55
  pour cut-out: 34.156,25.109 34.156,26.353 36.8,26.353 36.8,25.083
  pour cut-out: 31.25,25.2 31.25,26.3 33.754,26.3 33.754,25.196
  pour cut-out: 36.732,26.571 36.732,27.771 34.132,27.771 34.132,26.571
  pour cut-out: 39.2,23.303 39.2,27.312 41.465,27.312 41.465,23.303
  pour cut-out: 38.052,23.996 38.052,26.5 39.21,26.5 39.21,23.996
  pour cut-out: 30.3,28.9 30.3,30.9 32.4,30.9 32.4,28.9
  pour cut-out: 32.6,29.4 32.6,32.225 35.1,32.225 35.1,29.4
  pour cut-out: 35.325,29.75 35.325,32.85 36.775,32.85 36.775,29.75
  pour cut-out: 29.15,19.35 29.15,32.65 15.85,32.65 15.85,19.35
Bottom Layer:
  pour cut-out: 37.491,9.614 37.491,16.614 41.491,16.614 41.491,9.614
  pour cut-out: 12.591,46.329 32.422,46.329 32.422,49.629 12.578,49.629
GND (plane layer: these items are gaps in the copper):
  lines w0.2: 10.3,29 10.306,29.006
POWER (plane layer: these items are gaps in the copper):
  lines w0.5: -0.075,19.685 -0.075,23.155 11.34,23.155 23.12,11.375 29.523,11.375 29.523,-0.055 28.32,-0.055

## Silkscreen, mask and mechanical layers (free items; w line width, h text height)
Top Overlay:
  circle w0.2: c42.974,2.014 r1.25
  circle w0.2: c43,42 r1.25
  circle w0.2: c32.97,4.085 r0.85
  circle w0.2: c41.914,30.745 r0.85
  circle w0.2: c24.73,41.1 r0.85
  circle w0.2: c22.19,41.1 r0.85
  circle w0.2: c19.65,41.1 r0.85
  circle w0.2: c19.65,38.56 r0.85
  circle w0.2: c24.73,38.51 r0.85
  circle w0.2: c22.19,38.56 r0.85
  circle w0.2: c22.5,3 r2.7
  text "1" at 12.9,45.35 h1.52
  text "11" at 14.8,45.35 h1.52
  text "13" at 17.9,45.35 h1.52
  text "67" at 30.7,45.35 h1.52
  text "WH" at 21.32,42.392 h1.52
  text "UH" at 26.016,40.659 h1.52
  text "VL" at 16.586,40.539 h1.52
  text "GND" at 41.559,39.424 h1.52
  text "VH" at 26.124,38.02 h1.52
  text "WL" at 16.57,37.851 h1.52
  text "UL" at 21.458,36.388 h1.52
  text "BEMF_W" at 38.926,28.503 h1.52
  text "ATSAMD21MOTOR" at 6.227,27.037 h1.6 r90
  text "PWR" at 42.935,23.853 h1.52 r90
  text "h" at 3.216,22.039 h6 r90
  text "TMS" at 28.097,14.06 h1.2 r90
  text "TDI" at 30.115,14.06 h1.2 r90
  text "TCK" at 32.096,14.06 h1.2 r90
  text "GND" at 34.203,14.06 h1.2 r90
  text "GND" at 36.234,14.06 h1.52 r90
  text "CORTEX DBG" at 43.18,8.821 h1.52 r90
  text "RST" at 32.166,7.296 h1.2 r90
  text "VTG" at 28.109,7.203 h1.2 r90
  text "TDO" at 30.022,7.112 h1.2 r90
  text "VCC" at 36.131,6.545 h1.52 r90
  text "BOOT" at 34.128,6.346 h1.2 r90
  text "GND" at 41.467,3.737 h1.52
  text "STA" at 15.645,0.761 h1.52
  text "PWR" at 12.36,0.716 h1.52
  text "RESET" at 29.45,0.55 h1.52
Bottom Overlay:
  circle w0.2: c42.974,2.014 r1.25
  circle w0.2: c43,42 r1.25
  text "2" at 13.75,45.19 h1.52
  text "10" at 16.4,45.19 h1.52
  text "12" at 18.8,45.19 h1.52
  text "66" at 31.9,45.19 h1.52
  text "GND" at 44.467,39.474 h1.52
  text "Atmel Corp © 2015" at 8.835,24.854 h1.52 r270
  text "A08-2324 Rev 1" at 2.191,24.14 h2 r270
  text "p" at 1.891,15.473 h7 r270
  text "t" at 2.599,9.194 h7 r270
  text "GND" at 44.36,3.663 h1.52
  text "c" at 2.555,2.807 h5 r270
Mechanical 1:
  lines w0.2: 0.5,0 cw(c0.5,0.5) 0,0.5 0,43.5 cw(c0.5,43.5) 0.5,44 12.075,44 ccw(c12.075,44.5) 12.575,44.5 12.575,50 16.275,50 16.275,47.1 ccw(c16.875,47.1) 16.875,46.5 ccw(c16.875,47.1) 17.475,47.1 17.475,50 32.425,50 32.425,44.5 ccw(c32.925,44.5) 32.925,44 44.5,44 cw(c44.5,43.5) 45,43.5 45,0.5 cw(c44.5,0.5) 44.5,0 0.5,0 ; 0.5,0 ccw(c0.5,0) 0.5,0 ; 0.5,0 0.5,0
Mechanical 4:
  drawing of 187 lines, arcs and shapes, not listed
  text "SOLDER LEVEL" at -77.095,60.07 h1.78
  text "( SEE NOTE 2A )" at -54.108,60.07 h1.78
  text "COPPER PLATE" at -77.095,57.53 h1.78
  text "45 um" at -51.822,56.26 h1.78
  text "LAYER 1" at -110.369,54.99 h1.78
  text "COPPER FOIL" at -77.095,54.99 h1.78
  text "}" at -55.378,54.863 h4.44
  text "Prepregs" at -76.981,51.959 h1.78
  text "( SEE NOTE 1A )" at -41.173,51.967 h1.78
  text "125 um" at -62.507,51.648 h1.78
  text "COPPER FOIL" at -77.106,47.457 h1.78
  text "LAYER 2" at -110.369,47.452 h1.78
  text "35 um" at -55.81,47.427 h1.78
  text "CORE" at -76.395,34.559 h1.78
  text "400 um" at -62.044,34.559 h1.78
  text "0.81 mm +/- 10%" at -119.907,34.148 h1.78
  text "LAYER 3" at -110.269,21.182 h1.78
  text "COPPER FOIL" at -76.981,21.136 h1.78
  text "35 um" at -55.71,20.953 h1.78
  text "Prepregs" at -76.881,17.216 h1.78
  text "125 um" at -62.53,17.216 h1.78
  text "LAYER 4" at -110.369,13.08 h1.78
  text "COPPER FOIL" at -77.095,13.08 h1.78
  text "45 um" at -51.822,11.81 h1.78
  text "COPPER PLATE" at -77.095,10.54 h1.78
  text "}" at -55.378,10.413 h4.44
  text "SOLDER LEVEL" at -77.095,8 h1.78
  text "( SEE NOTE 2A )" at -54.108,8 h1.78
  text "NOTE  1A:  DIELECTRIC FR4" at -104.098,0.459 h1.78
  text "2A:  SURFACE PROTECTION: Chemical Gold" at -95.36,-2.077 h1.78
  text "THE BOARD MUST BE RoHS COMPLIANT" at -95.499,-7.197 h1.78
  text "DETAIL A ( CROSS-SECTION )" at -103.971,-16.051 h3.05
  text "SCALE = NONE" at -84.794,-20.623 h1.78
Drill Drawing:
  circle w0.254: c-0.685,-26.561 r0.511
  lines w0.254: -1.196,-33.206 -0.174,-33.206 -0.174,-32.184 -1.196,-32.184 -1.196,-33.206 ; -1.196,-30.139 -0.685,-29.884 -0.174,-30.139 -0.429,-29.628 -0.174,-29.117 -0.685,-29.372 -1.196,-29.117 -0.94,-29.628 -1.196,-30.139 ; -1.196,-23.75 -0.94,-23.75 -0.685,-24.006 -0.429,-23.75 -0.174,-23.75 -0.429,-23.495 -0.174,-23.239 -0.429,-23.239 -0.685,-22.983 -0.94,-23.239 -1.196,-23.239 -0.94,-23.495 -1.196,-23.75 ; -1.196,-19.917 -0.174,-19.917 -0.685,-20.939 -1.196,-19.917 ; -1.196,-17.361 -0.685,-17.872 -0.174,-17.361 -0.685,-16.85 -1.196,-17.361 ; -1.196,-14.55 -0.94,-14.55 -0.94,-14.805 -0.429,-14.805 -0.429,-14.55 -0.174,-14.55 -0.174,-14.039 -0.429,-14.039 -0.429,-13.783 -0.94,-13.783 -0.94,-14.039 -1.196,-14.039 -1.196,-14.55
  lines w0.381: -2.604,-34.126 48.282,-34.126 ; -2.604,-12.659 48.282,-12.659 ; 5.889,-37.193 5.889,-9.592 ; 15.058,-37.193 15.058,-9.592 ; 31.011,-37.193 31.011,-9.592 ; 37.783,-37.193 37.783,-9.592 ; -2.604,-37.193 48.282,-37.193 48.282,-9.592 -2.604,-9.592 -2.604,-37.193
  text "Symbol" at -0.764,-11.739 h1.83
  text "Hit Count" at 6.809,-11.739 h1.83
  text "Finished Hole Size" at 15.978,-11.739 h1.83
  text "Plated" at 31.931,-11.739 h1.83
  text "Hole Type" at 38.703,-11.739 h1.83
  text "1" at 6.809,-14.805 h1.52
  text "0.200mm (7.87mil)" at 15.978,-14.805 h1.52
  text "PTH" at 31.931,-14.805 h1.52
  text "Round" at 38.703,-14.805 h1.52
  text "1" at 6.809,-17.872 h1.52
  text "2.500mm (98.43mil)" at 15.978,-17.872 h1.52
  text "PTH" at 31.931,-17.872 h1.52
  text "Round" at 38.703,-17.872 h1.52
  text "2" at 6.809,-20.939 h1.52
  text "0.900mm (35.43mil)" at 15.978,-20.939 h1.52
  text "NPTH" at 31.931,-20.939 h1.52
  text "Round" at 38.703,-20.939 h1.52
  text "8" at 6.809,-24.006 h1.52
  text "0.400mm (15.75mil)" at 15.978,-24.006 h1.52
  text "PTH" at 31.931,-24.006 h1.52
  text "Round" at 38.703,-24.006 h1.52
  text "10" at 6.809,-27.072 h1.52
  text "0.650mm (25.59mil)" at 15.978,-27.072 h1.52
  text "PTH" at 31.931,-27.072 h1.52
  text "Round" at 38.703,-27.072 h1.52
  text "30" at 6.809,-30.139 h1.52
  text "0.203mm (8.00mil)" at 15.978,-30.139 h1.52
  text "PTH" at 31.931,-30.139 h1.52
  text "Round" at 38.703,-30.139 h1.52
  text "234" at 6.809,-33.206 h1.52
  text "0.300mm (11.81mil)" at 15.978,-33.206 h1.52
  text "PTH" at 31.931,-33.206 h1.52
  text "Round" at 38.703,-33.206 h1.52
  text "286 Total" at 6.809,-36.273 h1.52

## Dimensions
0,0.5 to 45,0.5 on Mechanical 4
0.5,0 to 12.575,50 on Mechanical 4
